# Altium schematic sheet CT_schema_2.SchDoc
size 276 x 169 mm
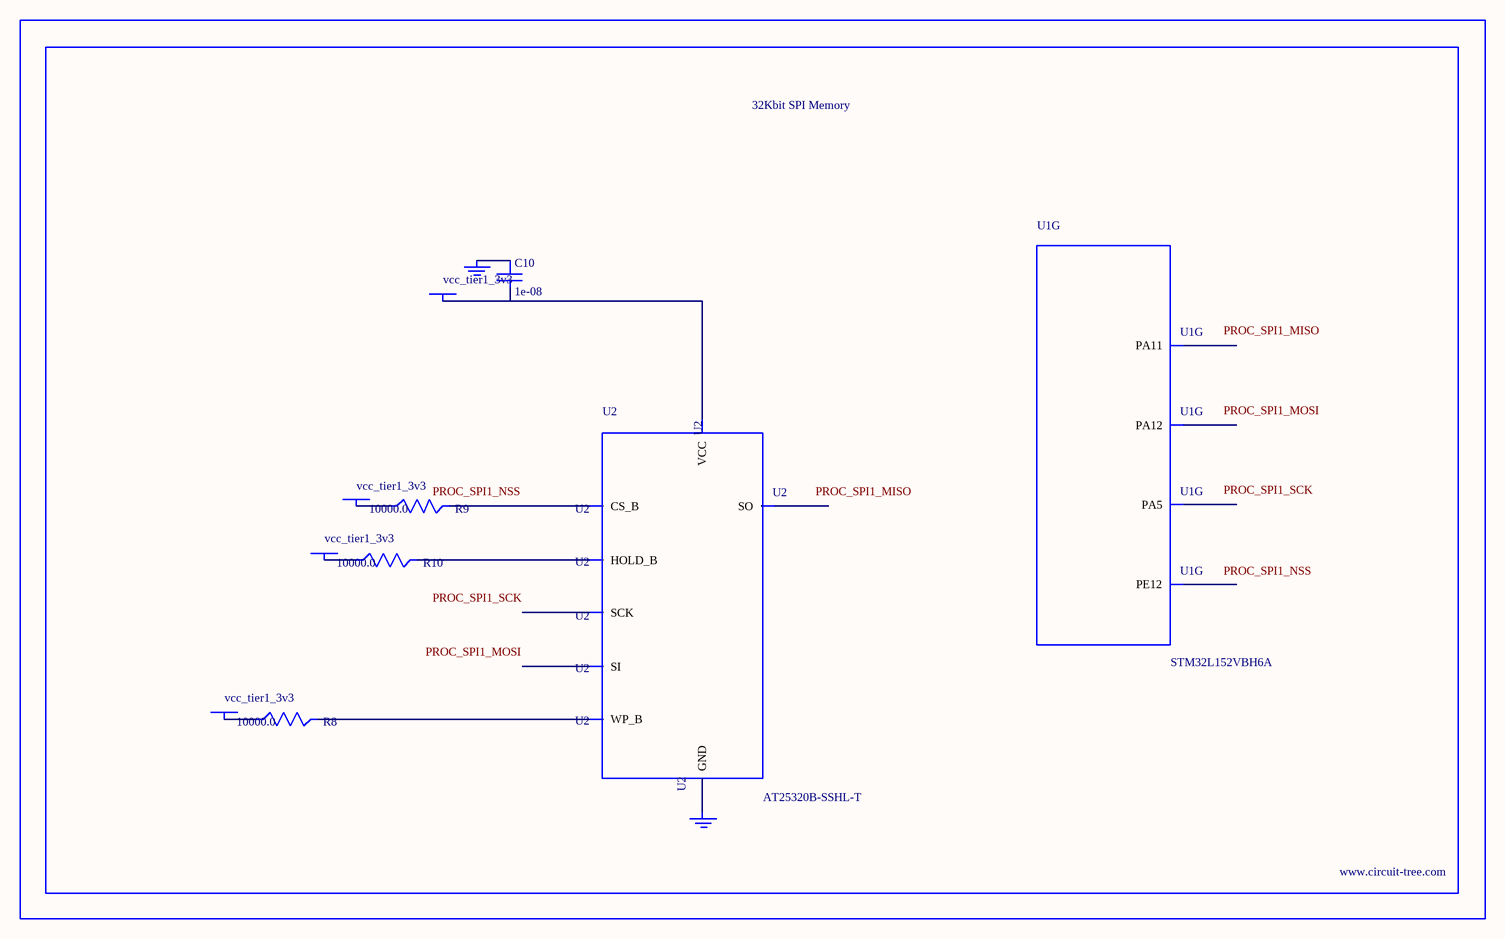
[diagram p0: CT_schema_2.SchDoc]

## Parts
BORDER1  (no value)
C10  1e-08  [C0402]
GND_INSTANCE_1_0  (no value)
GND_INSTANCE_1_1  (no value)
POWER_INSTANCE_1_0  vcc_tier1_3v3
POWER_INSTANCE_1_1  vcc_tier1_3v3
POWER_INSTANCE_1_2  vcc_tier1_3v3
POWER_INSTANCE_1_3  vcc_tier1_3v3
R8  10000.0  [R0603]
R9  10000.0  [R0603]
R10  10000.0  [R0603]
U1  STM32L152VBH6A  [UFBGA100]  (part G of 9)
U2  AT25320B-SSHL-T  [SOIC-8]

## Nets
NetC10_1: C10.1 GND_INSTANCE_1_0.0(GND)
NetC10_2: C10.2 POWER_INSTANCE_1_3.0(PWR) U2.8(VCC)
NetGND_INSTANCE_1_1_0: GND_INSTANCE_1_1.0(GND) U2.4(GND)
NetPOWER_INSTANCE_1_0_0: POWER_INSTANCE_1_0.0(PWR) R9.1
NetPOWER_INSTANCE_1_1_0: POWER_INSTANCE_1_1.0(PWR) R8.1
NetPOWER_INSTANCE_1_2_0: POWER_INSTANCE_1_2.0(PWR) R10.1
NetR8_2: R8.2 U2.3(WP_B)
NetR9_2: R9.2 U2.1(CS_B)
NetR10_2: R10.2 U2.7(HOLD_B)

Not connected (* = marked no-connect by the designer): U1 A12(PA12) B12(PA11) K4(PA5) L9(PE12); U2 2(SO) 5(SI) 6(SCK)

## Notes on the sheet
- Labels drawn without touching a wire or pin: PROC_SPI1_MISO, PROC_SPI1_MOSI, PROC_SPI1_NSS, PROC_SPI1_SCK

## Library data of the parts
BORDER1 = BORDER_PAGE1
C10 = C0402C103K3RAC
GND_INSTANCE_1_0 GND_INSTANCE_1_1 = GND
POWER_INSTANCE_1_0-POWER_INSTANCE_1_3 = PWR
R8-R10 = RC0603JR-0710KL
